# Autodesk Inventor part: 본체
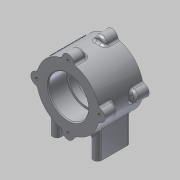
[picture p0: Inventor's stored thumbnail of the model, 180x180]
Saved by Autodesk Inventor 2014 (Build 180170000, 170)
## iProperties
Created: 2015-03
Part Number: 본체
Material: 알루미늄 6061
Document SubType Name: Modeling
Designer: MYHOME
Density: 2.71 g/cm^3
Appearance: 알루미늄 - 평지
Mass: 450.57 g
Surface Area: 333.077 cm^2
Volume: 166.262 cm^3
Author: MYHOME
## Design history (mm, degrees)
sketch "스케치1"
  geometry: C1 r 37 at (0, 0); 1 further point
  constraints: 1 centre point, 1 coincident
  dimensions: "d0" = 74 diameter of C1
extrude "돌출1" new body sketch "스케치1" distance "d1" = 52; taper "d2" = 0 deg
sketch "스케치2"
  geometry: C1 r 7 at (0, 37); C2 r 7 at (-37, 0); C3 r 7 at (0, -37); C4 r 7 at (37, 0); A1 r 37 centre (0, 0) between (0, 37) and (-37, 0) reference
  constraints: 4 centre point, 4 point on circle, 3 equal radius, 2 horizontal alignment, 2 vertical alignment
  dimensions: "d3" = 7 radius of C1
extrude "돌출2" join sketch "스케치2" distance "d4" = 15; taper "d5" = 0 deg
sketch "스케치3"
  geometry: A1 r 7 centre (0, 37) between (6.969, 36.338) and (-6.969, 36.338) reference; A2 r 7 centre (-37, 0) between (-36.338, 6.969) and (-36.338, -6.969) reference; A3 r 7 centre (0, -37) between (-6.969, -36.338) and (6.969, -36.338) reference; A4 r 7 centre (37, 0) between (36.338, -6.969) and (36.338, 6.969) reference; 4 further points
  constraints: 4 coincident
hole "구멍1" sketch "스케치3" at (0, 37), (-37, 0), (0, -37), (37, 0) diameter "d6" = 3.242; stored, may be unused: countersink angle "d10" = 90 deg, drill point angle "d12" = 118 deg; dims "d7" = 8, "d8" = 4, "d9" = 2, "d11" = 11
hole "구멍2" diameter "d15" = 42; stored, may be unused: countersink angle "d19" = 90 deg, drill point angle "d21" = 0 deg; dims "d16" = 8, "d17" = 47, "d18" = 22, "d20" = 30, "d31" = 10, "d32" = 10
hole "구멍3" diameter "d24" = 47; stored, may be unused: countersink angle "d28" = 90 deg, drill point angle "d30" = 0 deg; dims "d22" = 10, "d23" = 10, "d25" = 8, "d26" = 47, "d27" = 22, "d29" = 22
node "작업 평면1"
chamfer "모따기1" distance "d34" = 1; stored, may be unused: second distance "d35" = 2, angle "d36" = 45 deg
fillet "모깎기1" dims "d37" = 0.3
sketch "스케치4"
  geometry: L1 (0, 0)-(-21, 0); L2 (0, 0)-(-26.163, 26.163); A1 r 37 centre (0, 0) between (-6.969, 36.338) and (-36.338, 6.969) reference; 2 further points
  constraints: 4 end point, 1 coincident, 1 horizontal, 1 horizontal alignment, 1 point on circle, 1 other
  dimensions: "d38" = 45 deg angle of L1 L2
node "작업 평면2"
sketch "스케치5"
  geometry: L1 (20.767, 26)-(-20.767, 26) reference; L2 (-20.767, -26)-(20.767, -26) reference; 3 further points
  constraints: 1 midpoint, 1 vertical alignment, 1 other
  dimensions: "d39" = 26 distance from line of L1 point (0, 0)
feature "엠보싱1" sketch "스케치5" dims "d40" = 0.5, "d41" = 0
fillet "모깎기2" dims "d42" = 3
fillet "모깎기3" dims "d43" = 3
node "작업 평면3"
sketch "스케치6"
  geometry: L1 (-24, 46)-(-24, 6); L2 (-29, 41)-(-29, 11); L3 (-19, 11)-(-19, 41); L4 (24, 46)-(24, 6); L5 (29, 41)-(29, 11); L6 (19, 11)-(19, 41); L7 (-6.889, 52)-(6.889, 52) reference; L8 (-6.889, 0)-(6.889, 0) reference; L9 (9.104, 0)-(35.863, 0) reference; L10 (-35.863, 0)-(-9.104, 0) reference; L11 (-9.104, 52)-(-35.863, 52) reference; L12 (35.863, 52)-(9.104, 52) reference; L13 (37, 18)-(37, 34) reference; L14 (-37, 18)-(-37, 34) reference; L15 (0, 52)-(0, 0); L16 (0, 26)-(-32.045, 26); A1 r 5 centre (-24, 41) between (-19, 41) and (-29, 41); A2 r 5 centre (-24, 11) between (-29, 11) and (-19, 11); A3 r 5 centre (24, 41) between (29, 41) and (19, 41); A4 r 5 centre (24, 11) between (19, 11) and (29, 11); 2 further points
  constraints: 20 end point, 12 point on circle, 8 tangent, 4 centre point, 4 midpoint, 4 parallel, 4 point on line, 2 horizontal alignment, 1 perpendicular, 1 vertical
  dimensions: "d45" = 10 distance between parallel lines of L3 L2; "d46" = 10 distance between parallel lines of L5 L6; "d47" = 40 distance of L1.end L1.start; "d48" = 40 distance of L4.end L4.start; "d49" = 48 distance of point (24, 26) point (-24, 26); "d50" = 24 distance from line of L15 point (-24, 26)
extrude "돌출3" join sketch "스케치6" stored distance "d51" = 15; taper "d52" = 0 deg
fillet "모깎기4" dims "d53" = 3
sketch "스케치7"
  geometry: A1 r 5 centre (-24, 11) between (-29, 11) and (-19, 11) reference; A2 r 5 centre (-24, 41) between (-19, 41) and (-29, 41) reference; 3 further points
  constraints: 2 coincident
hole "구멍4" sketch "스케치7" at (-24, 41), (-24, 11) diameter "d54" = 4.459; stored, may be unused: countersink angle "d58" = 90 deg, drill point angle "d60" = 118 deg; dims "d55" = 6, "d56" = 47, "d57" = 22, "d59" = 8
node "솔리드1"
mirror "대칭1"
mirror "대칭2"
other parameters: "d33" = 26, "d44" = -56
